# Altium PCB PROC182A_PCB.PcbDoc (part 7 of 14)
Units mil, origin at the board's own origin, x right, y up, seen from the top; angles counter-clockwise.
Board outline 3168.31 x 3700.79 mil, 8 copper layers (Top Layer, L2_GND1, L3_SIG1, L4_PWR1, L5_PWR2, L6_SIG2, L7_GND2, Bottom Layer), stack 58.1 mil thick; 580 components, 391 nets, 8314 pads, 4370 vias.
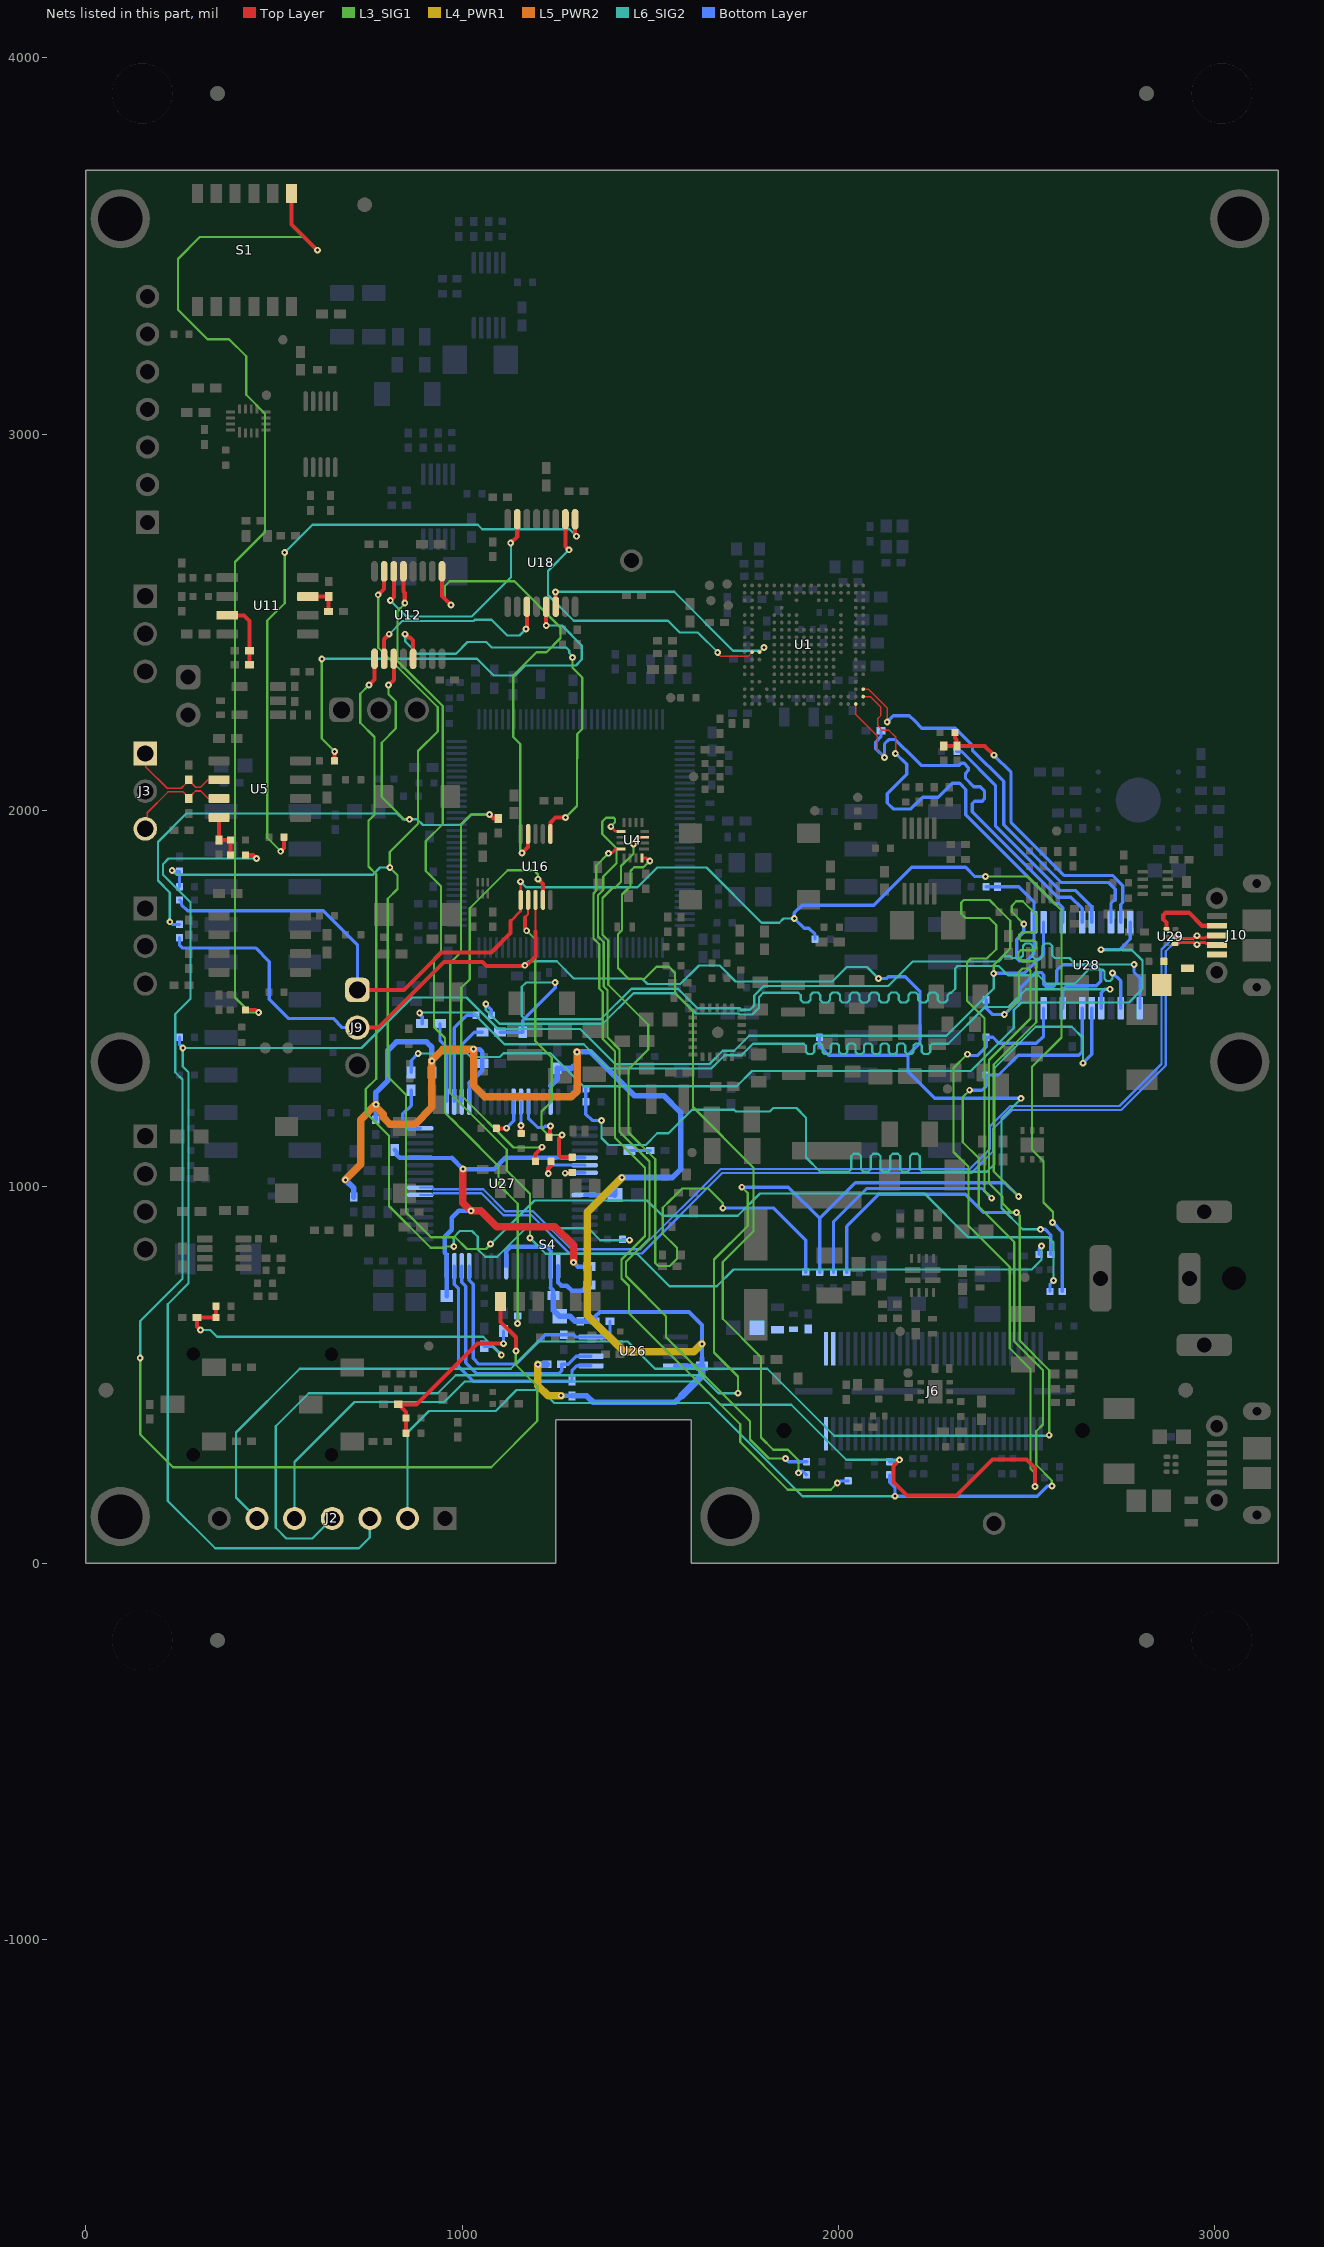
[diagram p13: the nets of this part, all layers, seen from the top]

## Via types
v1: diameter 13.77, hole 7, Top Layer to L2_GND1, tented both sides, 3444 vias
v2: diameter 18, hole 8, Top Layer to Bottom Layer, tented both sides, 911 vias
v3: diameter 13.77, hole 7, Top Layer to L2_GND1, tented top, 9 vias
v4: diameter 19.68, hole 7.87, Top Layer to Bottom Layer, 4 vias
v5: diameter 19.68, hole 7.87, Top Layer to Bottom Layer, tented both sides, 2 vias

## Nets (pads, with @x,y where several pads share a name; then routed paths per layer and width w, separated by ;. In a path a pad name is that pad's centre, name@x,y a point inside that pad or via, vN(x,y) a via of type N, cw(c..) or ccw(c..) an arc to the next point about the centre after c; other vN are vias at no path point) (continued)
CAN_FD_B_STB_CTRL: R133.1 S1.1 | length 2830.3
  Top Layer w10.8: R133.1@424.37,1470.14 450.83,1470.14 457.54,1463.43 v2(459.49,1463.43) ; S1.1@546.89,3639.18 546.89,3557.53 v2@615.88,3488.54
  L3_SIG1 w6: v2(459.49,1463.43) 436.82,1463.43 396.85,1503.4 396.85,2660.24 476.55,2739.94 476.55,3054.08 426.18,3104.45 426.18,3206.69 380.91,3251.97 323.82,3251.97 245.08,3330.71 245.08,3465.55 303.15,3523.62 581.13,3523.62 v2(616.05,3488.71)
CAN_FD_H: J3.3 R68.2 U5.7 | length 283.8
  Top Layer w4.3: J3.3@158.23,1951.41 163.25,1956.42 163.25,1994.38 218.41,2049.54 258.93,2049.54 266.49,2041.98 266.49,2041.51 273.71,2034.29 274.18,2034.29 R68.2@274.18,2031.85 ; R68.2@274.18,2034.64 275,2034.64 281.87,2041.51 281.87,2042.33 291.5,2051.95 305.38,2051.95 325.48,2031.85 U5.7@354.18,2031.85
CAN_FD_L: J3.1 R79.1 U5.6 | length 280.4
  Top Layer w4.3: J3.1@158.23,2151.41 159.7,2149.95 159.7,2115.98 216.34,2059.34 253.84,2059.34 266.49,2071.99 266.49,2072.19 R79.1@274.18,2079.88 ; R79.1@274.18,2081.85 R79.1@274.18,2079.88 ; U5.6@354.18,2081.85 324.93,2081.85 304.83,2061.75 292.32,2061.75 281.88,2072.19 R79.1@274.18,2079.88
CAN_FD_RX: R80.1 U18.5 | length 1216.1
  Top Layer w10.8: R80.1@661.32,2132.1 v2(661.32,2157.22) ; U18.5@1223.27,2541.56 1223.38,2541.44 1223.38,2491.76 v2(1223.5,2491.65)
  L3_SIG1 w6: v2(627.14,2402.65) 627.14,2191.4 v2(661.32,2157.22)
  L6_SIG2 w6: v2(627.14,2402.65) 628.06,2403.58 1039.61,2403.58 1084.25,2358.93 1141.19,2358.93 1167.77,2385.51 1302.58,2385.51 1318.08,2401.02 1318.08,2438.63 1265.06,2491.65 v2(1223.5,2491.65)
CAN_FD_TX: R78.1 U18.9 | length 1734.2
  Top Layer w10.8: v2(518.09,1891.85) 527.16,1900.92 R78.1@527.16,1929.49 ; U18.9@1300.04,2773.84 1300.04,2734.71 1304.03,2730.71 v2(1304.03,2728.77)
  L3_SIG1 w6: v2(518.09,1891.85) 482.32,1927.61 482.32,2504.74 528.65,2551.07 v2(528.65,2685.28)
  L6_SIG2 w6: v2(528.65,2685.28) 602.53,2759.16 1041.56,2759.16 1053.23,2747.48 1285.47,2747.48 1304.03,2728.92 v2(1304.03,2728.77)
CAN_FD_UARTA_RX: U1.R10 U18.6 | length 679
  Top Layer w4: U1.R10@1789.96,2420.95 v2(1801.98,2432.97)
  Top Layer w10.8: v2(1248.01,2581) 1248.43,2580.57 1248.43,2541.98 U18.6@1248.86,2541.56
  L6_SIG2 w6: v2(1248.01,2581) 1563.38,2581 1719.74,2424.64 1725.16,2424.64 1793.65,2424.64 v2(1801.98,2432.97)
CAN_FD_UARTA_TX: U1.T10 U18.10 | length 844.5
  Top Layer w4: v2(1678.86,2420.27) 1678.86,2417.38 1681.99,2414.25 1681.99,2414.01 1686.24,2409.75 1759.34,2409.75 1759.41,2409.69 U1.T10@1769.84,2420.95
  Top Layer w10.8: U18.10@1274.45,2773.84 1274.45,2701.85 v2@1283.85,2692.44
  L6_SIG2 w6: v2(1284.02,2692.61) 1228.01,2636.6 1228.01,2572.71 1296.4,2504.32 1528.36,2504.32 1546.86,2504.32 1578.1,2473.08 1626.05,2473.08 v2(1678.86,2420.27)
CAN_STB: R3.2 R71.2 R273.2 U5.8 | length 130
  Top Layer w10.8: U5.8@354.18,1981.85 R71.2@354.18,1921.85 R273.2@384.18,1921.85 R3.2@384.18,1881.85
CAN_STB_CTRL: R3.1 S4.1 | length 3404.8
  Top Layer w10.8: R3.1@424.54,1881.85 443.94,1881.85 v2(453.42,1872.37) ; S4.1@1102.05,696.11 1102.05,641.32 1142.63,600.73 v2@1142.63,564.15
  L3_SIG1 w6: v2(144.58,545.5) 144.58,342.66 231.61,255.63 1077.48,255.63 1199.92,378.07 1199.92,470.39 1142.8,527.5 v2(1142.8,564.32)
  L6_SIG2 w6: v2(144.58,545.5) 144.58,644.09 256.92,756.42 256.92,1285.62 237.87,1304.66 237.87,1459.33 278.65,1500.11 278.65,1756.12 205.04,1829.73 205.04,1857.47 219.94,1872.37 v2(453.42,1872.37)
CONN_5V: C92.1 C93.1 C96.2 J6.1 J6.2 J6.3 R30.2
DCA_LP_FTDI_HOST_INTR_1: R81.2 R261.2 R276.1 U28.10 | length 844.1
  Top Layer w10.8: R261.2@2279.02,2171.26 R276.1@2314.66,2171.26 2388.4,2171.26 v2(2412.68,2146.98) ; R81.2@2309.66,2207.46 2309.66,2192.43 2313.92,2188.16 R276.1@2313.92,2171.99
  Bottom Layer w8.7: v2(2412.68,2146.98) 2458.34,2101.33 2458.34,1968.09 2598.73,1827.7 2727.89,1827.7 2754.82,1800.77 2754.82,1755.73 2749.5,1750.41 U28.10@2749.5,1703.39
DCA_LP_FTDI_SPIA_CLK: U1.A16 U28.4 | length 1098.2
  Top Layer w4: U1.A16@2065.55,2302.84 2084.3,2302.84 2106.07,2281.07 ; 2106.07,2281.02 2112.52,2274.57 2112.52,2252.89 2103.92,2244.29 2103.92,2225.77 2116.6,2213.08 2134.36,2213.08 2151.5,2195.94 2151.5,2152.18 v2(2150.88,2151.56)
  Bottom Layer w8.7: v2(2150.88,2151.56) 2152.36,2151.56 2180.91,2123.02 2180.91,2096.81 2129.09,2044.99 2129.09,2020.1 2130.39,2018.79 2144.82,2004.36 2191.85,2004.36 2223.21,2035.72 2265.05,2035.72 2301.69,2072.36 2321.66,2072.36 2338.05,2055.98 2338.05,1989.12 2574.58,1752.59 2585.73,1752.59 2595.96,1742.37 U28.4@2595.96,1703.39
DCA_LP_FTDI_SPIA_CS: R246.1 U1.B17 U28.6 | length 1169.8
  Top Layer w4: U1.B17@2045.87,2283.16 2045.87,2254.99 2102.23,2198.63 2102.23,2161.2 v2(2122.12,2141.31)
  Bottom Layer w8.7: R246.1@2112.64,2211.9 2112.64,2195.7 2098.99,2182.05 2098.99,2164.44 v2(2122.12,2141.31) 2122.12,2177.1 2133.61,2188.58 2151.28,2188.58 2202.13,2137.73 2219.93,2119.93 2320.64,2119.93 2326.27,2125.56 2333.48,2125.56 2345.24,2113.8 2345.24,2106.59 2337.49,2098.85 2337.49,2085.16 2359.34,2063.31 2376.51,2063.31 2387.73,2052.09 2387.73,2030.96 2381.86,2025.09 2361.74,2025.09 2355.45,2018.8 2355.45,1996.33 2581.79,1769.99 2617.16,1769.99 2647.14,1740.01 U28.6@2647.14,1703.39
DCA_LP_FTDI_SPIA_MISO: R284.1 U28.7 | length 633.5
  Bottom Layer w8.7: R284.1@2314.15,2157 2326.64,2157 2416.96,2066.69 2416.96,1959.43 2588.99,1787.39 2630.12,1787.39 2672.73,1744.79 U28.7@2672.73,1703.39
DCA_LP_FTDI_SPIA_MOSI: U1.A15 U28.9 | length 1092.7
  Top Layer w4: U1.A15@2065.55,2322.53 2079.43,2322.53 2129.61,2272.35 2129.61,2235.61 v2(2129.35,2235.35)
  Bottom Layer w8.7: v2(2129.35,2235.35) 2145.82,2251.82 2188.38,2251.82 2202.13,2238.07 2221.17,2219.04 2309.95,2219.04 2355.85,2173.13 2355.85,2160.11 2438.63,2077.33 2438.63,1962.36 2592.4,1808.59 2717.78,1808.59 2734.98,1791.4 2734.98,1764.7 2723.91,1753.63 U28.9@2723.91,1703.39
DCA_LP_FTDI_UARTA_RX: U12.5 U16.6 | length 1119.4
  Top Layer w10.8: v2(848.58,2468.46) 857.66,2459.37 862.05,2459.37 869.69,2451.74 U12.5@869.69,2403.24 ; U16.6@1234.33,1937.85 1234.33,1967.62 1248.53,1981.82 v2(1274.86,1981.82)
  L3_SIG1 w6: v2(1274.86,1981.82) 1305.42,2012.38 1305.42,2137.94 1305.89,2138.42 1305.89,2203.53 1319.37,2217 1319.37,2353.41 1293.22,2379.55 v2(1293.22,2406.58)
  L6_SIG2 w6: v2(848.58,2468.46) 848.58,2449.12 880.82,2416.87 983.69,2416.87 1014.33,2447.51 1063.91,2447.51 1078.44,2432.99 1276.49,2432.99 1284.28,2425.2 1284.28,2418.77 1293.22,2409.83 v2(1293.22,2406.58)
DCA_LP_FTDI_UARTA_TX: U12.9 U16.9 | length 1253.4
  Top Layer w10.8: U12.9@946.46,2635.52 946.46,2569.55 v2@970.08,2545.93 ; v2(1159.01,1887.21) 1175.28,1903.47 U16.9@1175.28,1937.85
  L3_SIG1 w6: v2(970.25,2546.1) 954.15,2562.2 954.15,2595.9 967.26,2609 1138.91,2609 1261.53,2486.38 1261.53,2458.4 1224.04,2420.91 1197.38,2420.91 1135.65,2359.19 1135.65,2195.25 1154.18,2176.73 1154.18,1895.29 1159.01,1890.46 v2(1159.01,1887.21)
DCA_LP_HOST_INTR_1: J2.2 R42.2 R223.2 U28.19 | length 3822.9
  L3_SIG1 w6: v2(2348.55,1257.21) 2330.31,1238.98 2330.31,1118.66 2372.28,1076.69 2372.28,948.38 2466.83,853.83 2466.83,589.3 2543.31,512.82 2543.31,369.1 2525.29,351.08 2525.29,261.72 2566.78,220.24 v2(2566.78,205.6)
  L6_SIG2 w6: J2.2@854.92,119.45 854.92,347.72 911.95,404.75 1089.08,404.75 1144.75,460.42 1210.38,460.42 1244.66,426.14 1656.69,426.14 1904.34,178.48 v2(2150.09,178.48)
  Bottom Layer w8.7: R42.2@2136.06,235.06 2136.06,215.15 2150.09,201.11 v2(2150.09,178.48) ; v2@2150.48,178.48 2527.71,178.48 2554.52,205.29 2566.46,205.29 v2(2566.78,205.6) ; v2(2348.55,1257.21) 2381.42,1257.21 2392.35,1268.15 R223.2@2392.35,1297.45 2425.01,1297.45 2477.61,1350.04 2589.68,1350.04 2638.33,1350.04 2647.14,1358.85 U28.19@2647.14,1475.05
DCA_LP_RS232_RX: R61.1 R163.1 R178.1 U12.3 | length 4502.4
  Top Layer w10.8: v2(804.3,2333.27) 818.51,2347.48 U12.3@818.51,2403.24 ; v2(1072.67,1989.7) 1083.03,1979.33 R163.1@1096.46,1979.33
  L3_SIG1 w6: v2(804.3,2333.27) 804.3,2309.13 823.95,2289.48 823.95,2218.07 786.15,2180.26 786.15,2035.99 845.35,1976.79 v2(859.91,1976.79) ; v2(1072.67,1989.7) 1022.63,1989.7 996.71,1963.77 996.71,1623.39 968.29,1594.97 968.29,1248.86 1118.43,1098.72 1118.43,1043.93 1180.06,982.3 v2(1180.06,864.54)
  L6_SIG2 w6: v2(223.44,1704.32) 223.44,1782.56 191.86,1814.15 191.86,1916.36 267.4,1991.91 827.13,1991.91 842.25,1976.79 880.58,1976.79 895.85,1961.52 997.21,1961.52 1025.39,1989.7 v2(1072.67,1989.7) ; v2(1180.06,864.54) 1221.87,822.72 1464.89,822.72 1551.15,736.46 1676.67,736.46 1721.25,781.04 2513.32,781.04 2539.19,806.91 v2(2539.19,843.38)
  Bottom Layer w8.7: v2(223.44,1704.32) 230.32,1697.45 R178.1@249.2,1697.45 ; R61.1@2532.48,820.37 2532.48,834.15 2539.19,840.86 v2(2539.19,843.38)
DCA_LP_RS232_TX: R62.1 R156.1 R176.1 U12.15 | length 4562.3
  Top Layer w10.8: v2@776.78,2573.07 v2(776.95,2573.24) 792.92,2589.21 U12.15@792.92,2635.52
  L3_SIG1 w6: v2(776.95,2573.24) 776.95,2432.3 934.91,2274.33 934.91,2210.37 882.8,2158.25 882.8,1964.74 807.81,1889.75 v2(807.81,1848.89) 828.59,1828.12 828.59,1791.84 802.41,1765.67 802.41,1293.54 850.97,1244.98 850.97,932.91 917.39,866.48 981.8,866.48 1012.78,835.5 1063.44,835.5 1075.22,847.28 v2(1075.22,848.27)
  L6_SIG2 w6: v2(229.76,1840.97) 240.94,1829.79 762.94,1829.79 782.04,1848.89 v2(807.81,1848.89) ; v2(1075.22,848.27) 1076.21,848.27 1192.28,964.35 1491.24,964.35 1532.08,923.52 1732.28,923.52 1791.39,982.62 2228.19,982.62 2344.08,866.73 2556.77,866.73 2563.96,859.54 2571.29,852.21 v2(2571.29,751.51)
  Bottom Layer w8.7: v2(229.76,1840.97) 232.28,1840.97 235.8,1837.45 R156.1@249.2,1837.45 R176.1@249.2,1797.45 ; R62.1@2561.82,722.42 2561.82,742.04 v2(2571.29,751.51)
DCA_LP_SPIA_CLK: J2.3 R41.1 R210.1 U28.2 | length 6423
  L3_SIG1 w6: v2(2406.88,970.16) 2387.71,989.34 2387.71,1448.52 2341.55,1494.67 2341.55,1597.11 2351.32,1606.88 2393.79,1606.88 2418.68,1631.77 2418.68,1696.09 2400.39,1714.38 2337,1714.38 2325.76,1725.63 2325.76,1755.5 2332.97,1762.71 2400.89,1762.71 2428.36,1735.24 2456.34,1707.26 2456.34,1633.5 2412.22,1589.39 v2(2412.22,1566.86)
  L6_SIG2 w6: J2.3@754.92,119.45 754.92,68.9 726,39.98 343.88,39.98 217.87,165.99 217.87,688.71 273.31,744.16 273.31,1304.5 257.87,1319.94 v2(257.87,1369.43) 732.87,1369.43 866.61,1503.17 1011.62,1503.17 1095,1419.78 1313.68,1419.78 1406.82,1326.65 1657.04,1326.65 1692.46,1362.07 1723.06,1362.07 1762.71,1401.72 2286.56,1401.72 2412.22,1527.38 v2(2412.22,1566.86)
  Bottom Layer w8.7: R210.1@249.2,1397.45 249.2,1378.1 v2(257.87,1369.43) ; R41.1@1986.6,772.75 1986.6,908.09 2074.39,995.88 2381.16,995.88 v2(2406.88,970.16) ; v2(2412.22,1566.86) 2413.5,1568.14 2493.98,1568.14 2544.77,1618.93 U28.2@2544.77,1703.39
DCA_LP_SPIA_CS: J2.4 R39.1 R173.1 R177.2 U28.1 | length 4903.5
  L3_SIG1 w6: v2(1733.04,452.23) 1733.04,496.29 1669.15,560.18 1669.15,807.21 1758.51,896.57 1758.51,983.98 v2(1742.96,999.53) ; v2(2478.62,974.66) 2412.43,1040.84 2412.43,1325.2 2524.95,1437.71 2524.95,1593.63 2519.08,1599.49 2487.14,1599.49 2477.97,1608.67 2477.97,1622.65 2484.25,1628.94 2519.34,1628.94 2524.95,1634.54 2524.95,1649.87 2520.53,1654.29 2485.36,1654.29 2480.26,1659.39 2480.26,1669.84 2487.14,1676.72 2520.97,1676.72 2524.95,1680.69 2524.95,1723.66 2489.62,1758.98 2472.35,1758.98 2459.97,1746.61 2459.97,1731.09 v2(2492.18,1698.88)
  L6_SIG2 w6: J2.4@654.92,119.45 601.82,66.34 533.07,66.34 505.09,94.32 505.09,364.34 592.59,451.84 935.11,451.84 983.27,500 1633.52,500 1681.3,452.23 v2(1733.04,452.23)
  Bottom Layer w8.7: v2(1742.96,999.53) 1866.63,999.53 1949.84,916.32 ; R39.1@1949.84,772.75 1949.84,916.32 ; R177.2@2392.35,1797.45 R173.1@2422.35,1797.45 2479.19,1797.45 2519.18,1757.46 U28.1@2519.18,1703.39 2519.18,1619.83 2500.41,1601.06 2480.05,1601.06 2473.43,1607.68 2473.43,1657.69 2492.18,1676.45 v2(2492.18,1698.88) ; v2(2478.62,974.66) 2441.98,1011.3 2044.82,1011.3 1949.84,916.32
DCA_LP_SPIA_MISO: J2.5 R53.2 R221.2 U28.23 | length 4087.5
  Top Layer w10.8: v2(2161.63,275.08) 2145.67,259.12 2145.67,215.6 2181.33,179.93 2313.19,179.93 2409.29,276.04 2499.95,276.04 2522.1,253.88 v2(2522.1,204.37)
  L3_SIG1 w6: v2(2342.3,1352.6) 2305.48,1315.78 2305.48,1092.93 2345.02,1053.39 2345.02,897.09 2454.83,787.29 2454.83,571.25 2510.3,515.78 2510.3,251.68 2522.1,239.88 v2(2522.1,204.37)
  L6_SIG2 w6: J2.5@554.92,119.45 554.92,269.49 714.36,428.93 952.55,428.93 1006.89,483.27 1624.36,483.27 1686.47,421.15 1874.44,421.15 2020.51,275.08 v2(2161.63,275.08)
  Bottom Layer w8.7: R53.2@2135.45,270.03 2156.58,270.03 v2(2161.63,275.08) ; v2@2349.57,1349.16 2368.97,1349.16 2392.35,1372.55 R221.2@2392.35,1397.45 2410.37,1397.45 2426.24,1381.58 2525.77,1381.58 2544.77,1400.59 U28.23@2544.77,1475.05
DCA_LP_SPIA_MOSI: J2.6 R52.1 R201.2 U28.21 | length 5429.5
  L3_SIG1 w6: v2(2440.54,1457.95) 2479.6,1497.01 2479.6,1571.64 2488.43,1580.47 2503.15,1580.47 2509.98,1573.64 2509.98,1447.49 2399.71,1337.22 2399.71,1009.8 2434.75,974.76 2434.75,957.09 2459.48,932.37 v2(2472.96,932.37) 2481.12,924.21 2481.12,591.97 2559.75,513.35 v2(2559.75,340.51)
  L6_SIG2 w6: J2.6@454.92,119.45 399.19,175.18 399.19,347.7 568.58,517.08 1128.94,517.08 1201.42,589.57 1439.96,589.57 1512.44,517.09 1810.67,517.09 1988.8,338.96 2558.19,338.96 v2(2559.75,340.51)
  Bottom Layer w8.7: R52.1@2021.6,773.19 2021.6,895.09 2106.84,980.33 2336.41,980.33 2384.37,932.37 v2(2472.96,932.37) ; R201.2@2392.35,1497.45 2392.35,1474.71 2409.11,1457.95 v2(2440.54,1457.95) 2483.02,1500.43 2483.02,1528.44 2524.42,1569.84 2538.22,1569.84 2545.27,1562.79 2545.27,1538.06 2551.3,1532.03 2570,1532.03 2579.83,1541.86 2579.83,1575.15 2595.03,1590.35 2680.53,1590.35 2696.68,1574.2 2696.68,1546.08 2685.26,1534.66 2605.6,1534.66 2595.96,1525.01 U28.21@2595.96,1475.05
DCA_LP_UARTA_RX: J9.2 R152.2 R198.1 R212.1 U16.3 | length 3868.7
  Top Layer w6: 1194.96,1678.51 U16.3@1194.96,1762.65
  Top Layer w10.8: J9.2@721.75,1423.37 777.37,1423.37 952.04,1598.03 1054.65,1598.03 1065.2,1587.48 v2@1169.76,1587.48 ; v2(1166.6,1588.75) 1168.55,1588.75 1172.15,1592.35 1174.63,1592.35 1194.96,1612.68 1194.96,1678.51
  L6_SIG2 w6: v2(1166.6,1588.75) 1166.6,1589.85 1176.11,1599.37 1251.1,1599.37 1296.59,1553.88 1477.53,1553.88 1492.5,1538.91 1579.69,1538.91 1629.04,1588.26 1684.12,1588.26 1726.48,1545.89 1983.49,1545.89 2021.86,1584.26 2075.59,1584.26 v2(2105.96,1553.89) ; v2(2485.02,1235.48) 2485.02,1234.29 2463.11,1212.39 2433.03,1182.31 2433.03,944.02 2489.49,887.55 v2(2536.34,887.55)
  Bottom Layer w8.7: R198.1@249.2,1662.45 249.2,1641.77 255.85,1635.13 451.25,1635.13 487.46,1598.92 487.46,1498.29 538.1,1447.65 657.51,1447.65 681.79,1423.37 J9.2@721.75,1423.37 ; R212.1@1949.2,1397.45 1949.2,1374.67 1973.59,1350.28 2184.3,1350.28 ; v2(2105.96,1553.89) 2128.12,1553.89 2132.36,1558.13 2177.13,1558.13 2216.52,1518.74 2216.52,1382.5 2184.3,1350.28 ; v2(2485.02,1235.48) 2255.81,1235.48 2184.3,1306.99 2184.3,1350.28 ; v2(2536.34,887.55) 2548.78,887.55 2563.98,872.35 R152.2@2563.98,820.87
DCA_LP_UARTA_TX: J9.1 R153.2 R180.1 R182.1 U16.1 | length 4070.8
  Top Layer w7: 1128.83,1705.92 1155.59,1732.68 U16.1@1155.59,1762.65 1155.59,1810.19 v2(1154.8,1810.99)
  Top Layer w10.8: J9.1@721.75,1523.37 845.57,1523.37 945.07,1622.86 1077.37,1622.86 1128.83,1674.32 1128.83,1705.92
  L3_SIG1 w6: v2(2390.55,1824.57) 2502.69,1824.57 2592.05,1735.22 2592.05,1397.34 2514.05,1319.34 2514.05,1098.63 2544.67,1068.01 2544.67,958.6 2569.6,933.67 2569.6,906.58 v2(2568.81,905.78)
  L6_SIG2 w6: v2(1154.8,1810.99) 1169.54,1796.25 1466.17,1796.25 1518.34,1848.42 1649.1,1848.42 1795.65,1701.87 1842.59,1701.87 1853.97,1713.25 v2(1882.65,1713.25)
  Bottom Layer w8.7: R180.1@249.2,1762.45 254.2,1757.45 254.2,1750.32 270.49,1734.03 631.49,1734.03 721.75,1643.77 J9.1@721.75,1523.37 ; R182.1@1937.71,1658.52 1937.71,1670.86 1920.99,1687.58 1908.32,1687.58 v2(1882.65,1713.25) 1882.65,1728.04 1903.01,1748.41 2093.6,1748.41 2194.62,1849.43 2337.7,1849.43 2362.56,1824.57 v2(2390.55,1824.57) ; v2(2568.81,905.78) 2594.47,880.12 R153.2@2594.47,722.42
DCA_TCK: R38.2 U4.16 | length 2124
  Top Layer w7: U4.16@1477.36,1874.02 1488.92,1874.02 1496.73,1866.21 v2(1498.62,1866.21)
  L3_SIG1 w6: v2(1498.62,1866.21) 1482.1,1849.69 1457.27,1849.69 1447.22,1839.64 1447.22,1799.4 1424.53,1776.71 1424.53,1682.25 1413.95,1671.68 1413.95,1581.44 1442.62,1552.77 1484.18,1552.77 1516.22,1584.82 1549.44,1584.82 1565.83,1568.44 1565.83,1514.33 1613.19,1466.96 1613.19,1340.77 1613.18,1212.5 1774.29,1051.39 1774.29,882.19 1692.5,800.4 1692.5,649.64 1794.29,547.85 1794.29,334.65 1826.77,302.17 1865.88,302.17 1893.95,274.09 v2(1893.95,240.69)
  Bottom Layer w8.7: v2(1893.95,240.69) 1896.01,240.69 1900.2,244.87 1905.51,244.87 1914.83,235.55 R38.2@1914.83,235.06
DCA_TDI: R37.1 U4.3 | length 2062.5
  Top Layer w7: v2(1454.98,1910.64) 1454.98,1913.18 1470.93,1929.13 U4.3@1485.24,1929.13
  L3_SIG1 w6: v2(1454.98,1910.64) 1454.98,1885.58 1421.98,1852.58 1421.98,1810.9 1406.81,1795.73 1401.11,1795.73 1372.85,1767.47 1372.85,1670.31 1388.11,1655.05 1388.11,1537.4 1494.38,1431.13 1494.38,1365.44 1441.86,1312.92 1441.86,1144.66 1512.82,1073.69 1512.82,798.15 1520.87,790.1 1551.61,790.1 1570.63,809.12 1570.63,838.52 1533.18,875.96 1533.18,944.82 1553.45,965.09 1553.74,965.09 1565.45,976.8 1565.45,977.09 1584.49,996.13 1653.92,996.13 1692.67,957.37 v2(1692.67,943.52)
  Bottom Layer w8.7: v2(1692.67,943.52) 1693.09,943.93 1827.76,943.93 1912.63,859.06 R37.1@1912.63,773.64
DCA_TDO: R34.2 U4.9 | length 2170
  Top Layer w7: v2(1394.94,1957.23) 1407.29,1944.88 U4.9@1422.24,1944.88
  L3_SIG1 w6: v2(1394.94,1957.23) 1406.35,1968.65 1406.35,1977.7 1402.83,1981.21 1382.2,1981.21 1372.21,1971.22 1372.21,1937.53 1410.03,1899.71 1410.03,1860.34 1374.73,1825.03 1374.73,1788.86 1360.85,1774.98 1360.85,1665.34 1376.11,1650.08 1376.11,1532.43 1385.91,1522.63 1385.91,1397.93 1418.38,1365.46 1418.38,1146.91 1497.58,1067.71 1497.58,863.59 1435.23,801.24 1435.23,763.17 1541.81,656.59 1541.81,600.65 1764.8,377.66 1764.8,328.89 1815.28,278.41 v2(1859.04,278.41)
  Bottom Layer w8.7: v2(1859.04,278.41) 1859.04,277.92 1866.93,270.03 R34.2@1915.43,270.03
DCA_TMS: R40.2 U4.12 | length 2180.8
  Top Layer w7: v2(1389.15,1886.55) 1391.25,1888.65 1398.95,1888.65 1407.93,1897.64 U4.12@1422.24,1897.64
  L3_SIG1 w6: v2(1389.15,1886.55) 1356.28,1853.68 1356.28,1787.38 1348.85,1779.95 1348.85,1660.37 1364.11,1645.11 1364.11,1527.46 1373.91,1517.66 1373.91,1392.96 1406.38,1360.49 1406.38,1130.43 1485.58,1051.22 1485.58,869.56 1423.23,807.21 1423.23,757.09 1443.62,736.7 1443.62,664.67 1738.59,369.71 1738.59,322.38 1865.27,195.7 1979.06,195.7 v2(1996.62,213.26)
  Bottom Layer w8.7: v2(1996.62,213.26) 1999.14,213.26 2004.44,218.56 2024.51,218.56 R40.2@2025.44,219.5
EECLK: R167.1 U26.2 U27.62 | length 634.8
  Bottom Layer w8.7: U27.62@999.11,789.79 999.11,746.27 1009.67,735.71 1009.67,533.43 1039.17,503.94 1256.12,503.94 1264.36,512.18 R167.1@1264.36,528.88 ; R167.1@1264.39,528.85 1281.86,528.85 1303.33,550.33 U26.2@1342.51,550.33
EECS: R168.1 U26.1 U27.63 | length 672.8
  Bottom Layer w8.7: U27.63@979.43,789.79 979.43,741.05 990.47,730.01 990.47,522.59 1029.46,483.6 1290.93,483.6 R168.1@1291.83,484.49 1291.83,511.46 1305.11,524.74 U26.1@1342.51,524.74
EEDATA: R184.1 R185.1 U26.4 U27.61 | length 690.9
  Bottom Layer w8.7: U27.61@1018.8,789.79 1018.8,752.35 1029.4,741.76 1029.4,544.54 1044.52,529.42 1142.91,529.42 1220.8,607.31 R185.1@1270.18,607.31 1296.26,607.31 1302.07,601.51 U26.4@1342.51,601.51 1384.36,601.51 1392.88,610.03 R184.1@1392.88,643.29
EEPROM_A2: R161.1 R162.2 U11.3 | length 95
  Top Layer w10.8: U11.3@590.19,2568.79 R162.2@645.19,2568.79 R161.1@645.19,2528.79
EEPROM_WPn: R157.1 R158.2 U11.7 | length 181.4
  Top Layer w10.8: U11.7@376.18,2518.23 420.37,2518.23 435.36,2503.23 R157.1@435.36,2424.24 R158.2@435.36,2387.24
FTDI_3V3: C138.1 C149.2 C150.1 C151.2 C152.1 C153.1 L2.1 L3.1 L7.2 R167.2 R168.2 R184.2 R237.1 U26.8 U27.20 U27.31 U27.42 U27.50 U27.56 | length 5061.4
  L5_PWR2 w20: v2(689.55,1019.13) 730.24,1059.82 730.24,1178.9 v2(770.93,1219.59) ; v2@771.65,1211.62 790.03,1193.24 790.03,1185.49 808.41,1167.11 875.07,1167.11 919.56,1211.6 v2(919.56,1334.86) ; v2@919.43,1336.22 919.75,1336.54 949.22,1366.01 v2(1030.44,1366.01) 1030.44,1269.36 1060.68,1239.13 1290.21,1239.13 1305.57,1254.48 1305.57,1358.13 v2(1304.88,1358.82)
  L4_PWR1 w20: v2(1201.29,528.54) 1201.29,472.57 1228.49,445.37 v2(1263.15,445.37) ; v2(1424.21,1024.61) 1332.51,932.9 1332.51,659.35 1430.18,561.67 1615.44,561.67 v2(1637.22,583.46)
  Bottom Layer w10: U27.20@1018.8,1226.8 1018.8,1275.29 ; 1235.32,731.78 1235.32,754.55 1235.34,831.23 ; U27.31@1235.34,1226.8 1235.34,1269.13 ; U27.42@1325.89,978.77 C151.2@1405.89,978.77
  Bottom Layer w11: U27.56@1117.32,789.79 1117.32,831.23 ; R184.2@1353.51,643.29 1353.51,655.64 1366.14,668.26 1602.56,668.26 1637.22,633.6 v2(1637.22,583.46) 1636.84,583.08 1636.84,546.39
  Bottom Layer w12: 770.93,1204.59 770.93,1199.41 770.93,1178.66 L3.1@770.99,1178.6 ; 1018.8,1275.29 1053.81,1310.3 1053.81,1358.98 1046.78,1366.01 v2(1030.44,1366.01) ; 1117.32,831.23 1118.68,831.23 1128.38,840.92 1225.61,840.92 1235.31,831.23 ; v2(1201.29,528.54) v2@1201.46,528.71 ; R167.2@1224.82,528.71 R167.2@1224.99,528.88 ; 1235.34,731.76 1242.32,724.78 C150.1@1242.32,711.79 ; v2(1263.15,445.37) 1263.27,445.25 1291.7,445.25 R168.2@1291.83,445.12
  Bottom Layer w13: U26.8@1566.92,524.74 C138.1@1636.84,524.74 ; 1636.84,546.39 1636.84,524.81 C138.1@1636.92,524.74
  Bottom Layer w15: v2(689.55,1019.13) 712.28,996.41 L2.1@712.28,973.04 ; 770.93,1204.59 770.93,1250.86 802.08,1282.01 802.08,1361.87 825.8,1385.59 905.26,1385.59 919.43,1371.42 919.43,1334.99 v2(919.56,1334.86) ; R237.1@919.5,1304.08 v2@919.5,1336.15 ; 1235.34,1269.13 1252.76,1286.55 C152.1@1252.76,1315.55 1290.86,1315.55 1304.88,1329.58 v2(1304.88,1358.82) 1341.8,1358.82 1458.2,1242.41 1536.35,1242.41 1580.52,1198.24 1580.52,1046.87 1558.61,1024.97 1423.74,1024.97 1405.89,1007.11 C151.2@1405.89,978.77 ; C150.1@1242.32,711.79 1242.32,672.57 1258.43,656.45 C149.2@1259.42,656.45 1286.61,656.45 1299.77,643.29 L7.2@1313.51,643.29 R184.2@1353.51,643.29 ; R168.2@1291.83,445.12 1331.17,445.12 1348.22,428.07 1566.03,428.07 1583.08,445.12
  Bottom Layer w18: v2@1201.46,528.71 R167.2@1224.82,528.71
  Bottom Layer w20: 1583.08,445.12 1636.84,498.89 1636.84,524.74 C138.1@1636.84,524.81
FTDI_12C_SDA_IN: R100.1 U27.27 | length 84.5
  Top Layer w10.8: v2(1156.57,1162.98) 1156.66,1162.89 1156.66,1142.48 R100.1@1156.74,1142.4
  Bottom Layer w8.7: v2(1156.57,1162.98) U27.27@1156.59,1226.8
FTDI_12C_SDA_OUT: R102.1 U27.28 | length 145.8
  Top Layer w10.8: R102.1@1231.31,1131.76 1233.59,1134.04 1233.59,1160.29 v2(1234.97,1161.67)
  Bottom Layer w8.7: U27.28@1176.28,1226.8 1176.28,1182.9 1201.18,1158 1217.27,1158 1220.94,1161.67 v2(1234.97,1161.67)
FTDI_DCA_LP_RS232_RX: U12.2 U18.3 | length 534.6
  Top Layer w10.8: U12.2@792.92,2403.24 792.92,2455.11 v2(806.27,2468.46) ; v2@1169.26,2482.04 v2(1169.43,2482.21) 1172.09,2484.87 U18.3@1172.09,2541.56
  L6_SIG2 w6: v2(806.27,2468.46) 841.23,2503.41 1030.35,2503.41 1033.61,2506.68 1078.29,2506.68 1119.67,2465.3 1152.52,2465.3 v2(1169.43,2482.21)
FTDI_DCA_LP_RS232_TX: U12.14 U18.15 | length 624.6
  Top Layer w10.8: v2@809.06,2558.07 v2(809.22,2558.24) 818.51,2567.53 U12.14@818.51,2635.52 ; v2(1128.94,2710.63) 1146.5,2728.19 U18.15@1146.5,2773.84
  L6_SIG2 w6: v2(809.22,2558.24) 852.05,2515.41 1025.38,2515.41 1129.88,2619.92 1129.88,2709.69 v2(1128.94,2710.63)
FTDI_HOST_INTR_1: R216.2 R217.2 U28.18 | length 2494.4
  L6_SIG2 w6: v2(1370.15,1176.78) 1370.15,1129.99 1388.68,1111.46 1487.7,1111.46 1518.7,1142.46 1548.1,1142.46 1610.68,1205.05 1723.22,1205.05 1727.92,1200.35 1817.48,1200.35 1826.72,1209.58 1888.01,1209.58 1913.49,1184.11 1913.49,1078.57 1951.7,1040.36 1997.36,1040.36 2027.15,1040.36 2033.65,1046.86 2033.65,1081.89 2040.15,1088.39 2053.15,1088.39 2059.65,1081.89 2059.65,1046.81 2066.15,1040.31 2079.15,1040.31 2085.65,1046.81 2085.65,1081.89 2092.15,1088.39 2105.15,1088.39 2111.65,1081.89 2111.65,1046.81 2118.15,1040.31 2131.15,1040.31 2137.65,1046.81 2137.65,1081.89 2144.15,1088.39 2157.15,1088.39 2163.65,1081.89 2163.65,1046.81 2170.15,1040.31 2183.15,1040.31 2189.65,1046.81 2189.65,1081.89 2196.15,1088.39 2209.15,1088.39 2215.65,1081.89 2215.65,1046.86 2222.15,1040.36 2251.15,1040.36 2393.94,1040.36 2413.39,1059.8 2413.39,1315.12 2523.93,1425.67 2619.44,1425.67 2649.26,1395.84 v2(2649.26,1328.81)
  Bottom Layer w8.7: R216.2@1328.65,1261.32 R217.2@1328.65,1226.32 1328.65,1193.46 1345.33,1176.78 v2(1370.15,1176.78) ; v2(2649.26,1328.81) 2672.73,1352.28 U28.18@2672.73,1475.05
FTDI_I2C_SCL: R96.1 U27.26 | length 105.5
  Top Layer w10.8: R96.1@1090.96,1155.7 1091.12,1155.87 1117.41,1155.87 v2(1117.57,1156.03)
  Bottom Layer w8.7: v2(1117.57,1156.03) 1136.91,1175.37 U27.26@1136.91,1226.8
FTDI_MISO: R189.1 U27.18 | length 267.3
  Bottom Layer w8.7: U27.18@979.43,1226.8 979.41,1422.58 1012.74,1455.91 R189.1@1037.18,1455.91
FTDI_MOSI: R187.1 U27.17 | length 214.8
  Bottom Layer w8.7: R187.1@941.09,1433.88 941.09,1389.97 959.74,1371.31 U27.17@959.74,1226.8
FTDI_RS232_RX: R120.2 U12.1 | length 2366.5
  Top Layer w10.8: v2(752.42,2333.27) 767.33,2348.18 U12.1@767.33,2403.24
  L3_SIG1 w6: v2(752.42,2333.27) 729.63,2310.48 729.63,2233.12 767.51,2195.24 767.51,1989.11 751.02,1972.62 751.02,1851.64 771.68,1830.98 771.68,1287.62 744.09,1260.04 744.09,1197.75 805.55,1136.29 805.55,949.59 916.6,838.54 954.91,838.54 958.33,841.95 977.61,841.95 v2(977.83,842.17)
  L6_SIG2 w6: v2(977.83,842.17) 977.83,866.69 993.96,882.82 1025.96,882.82 1041.22,867.56 1041.22,834.19 1061.14,814.27 1093.36,814.27 1169.09,890 1335.46,890 1366.84,858.62 v2(1444.59,858.62)
  Bottom Layer w8.7: R120.2@1426.24,860.66 1427.26,859.64 1443.57,859.64 v2(1444.59,858.62)
FTDI_RS232_TX: R121.2 U12.13 | length 2213.5
  Top Layer w10.8: U12.13@844.1,2635.52 844.1,2582.03 847.61,2578.52 v2(847.61,2551.43)
  L3_SIG1 w6: v2(847.61,2551.43) 847.61,2549.33 828.58,2530.29 828.58,2397.64 948.48,2277.74 948.48,1963.86 903.55,1918.93 903.55,1839.27 944.07,1798.74 944.07,1626.43 925.03,1607.38 925.03,1425.27 954.7,1395.59 954.7,1197.13 984.83,1167.01 984.83,1166.81 996.54,1155.09 996.75,1155.09 1096.46,1055.38 1096.46,1006.25 1147.53,955.18 1147.53,637.83 v2(1147.12,637.41)
  Bottom Layer w8.7: v2(1147.12,637.41) 1147.43,637.72 1147.43,657.46 R121.2@1147.74,657.77
FTDI_SOP0: R13.1 R43.2 R235.1 R249.2 | length 998.3
  Top Layer w10.8: v2(305.12,620.08) 295.94,629.26 R13.1@295.94,653.31 R43.2@345.94,653.31 R235.1@345.94,683.31
  L6_SIG2 w6: v2(305.12,620.08) 330.82,620.08 349.02,601.88 1056.08,601.88 v2(1104.16,553.8)
  Bottom Layer w8.7: R249.2@1058.84,576.72 1081.24,576.72 v2(1104.16,553.8)
FTDI_SOP1: R16.1 R67.2 R244.1 R248.2 | length 464.6
  Top Layer w10.8: R244.1@850.79,346.19 R67.2@850.79,386.19 850.79,401.94 R16.1@830.34,422.39 878.92,422.39 1040.29,583.76 v2(1109.73,583.76)
  Bottom Layer w8.7: v2(1109.73,583.76) R248.2@1109.7,617.41
FTDI_SPI_CLK: R186.2 U28.11 | length 2494.5
  L6_SIG2 w6: v2(883.4,1354.86) 955.53,1354.86 955.82,1355.15 1013.02,1355.15 1022.89,1345.28 1099.82,1345.28 1109.69,1355.15 1234.53,1355.15 1322.17,1267.51 1729.51,1267.51 1770.14,1308.14 2351.44,1308.14 2465.55,1422.25 2465.55,1470.04 2485.9,1490.39 2771.44,1490.39 2807.51,1526.47 2807.51,1601.37 2778.47,1630.42 v2(2697.03,1630.42)
  Bottom Layer w8.7: R186.2@864.5,1304.02 864.5,1335.95 v2(883.4,1354.86) ; v2(2697.03,1630.42) 2746.78,1630.42 2775.09,1658.73 U28.11@2775.09,1703.39
FTDI_SPI_CS: R99.1 R209.2 U28.13 | length 2420.8
  L6_SIG2 w6: v2(1247.27,1543.1) 1170.17,1543.1 1158.74,1531.68 1158.74,1454.37 1167.61,1445.5 1368.61,1445.5 1450.02,1526.91 1573.22,1526.91 1625.26,1474.87 1737.56,1474.87 1741.47,1470.96 1765.08,1470.96 1776.43,1482.32 1776.43,1508.93 1801.4,1533.89 2132.31,1533.89 2197.27,1598.86 2424.81,1598.86 2438.93,1612.97 2456.23,1612.97 2460.84,1608.36 2462.59,1608.36 2483.38,1608.36 2489.88,1614.86 2489.88,1640.3 2496.38,1646.8 2509.38,1646.8 2515.88,1640.3 2515.88,1611.74 2522.38,1605.24 2535.38,1605.24 2541.88,1611.74 2541.88,1640.3 2548.38,1646.8 2561.38,1646.8 2567.88,1640.3 2567.88,1614.86 2574.38,1608.36 2603.38,1608.36 2613.83,1608.36 2631.1,1591.08 v2(2785.36,1591.08)
  Bottom Layer w8.7: R209.2@1101.06,1411.22 R99.1@1161.06,1411.22 1161.06,1442.44 1247.27,1528.66 v2(1247.27,1543.1) ; v2@2784.98,1591.01 2784.98,1570.97 2800.68,1555.27 U28.13@2800.68,1475.05
FTDI_SPI_MISO: R189.2 U28.15 | length 2369.7
  L6_SIG2 w6: v2(1062.97,1485.76) 1062.97,1469.93 1099.4,1433.5 1373.58,1433.5 1454.99,1514.91 1567.36,1514.91 1621.19,1461.09 1734.37,1461.09 1736.99,1458.47 1770.88,1458.47 1788.43,1476.02 1788.43,1503.96 1800.16,1515.69 1846.44,1515.69 1893.15,1515.69 1899.65,1509.19 1899.65,1496.45 1906.15,1489.95 1919.15,1489.95 1925.65,1496.45 1925.65,1509.99 1932.15,1516.49 1945.15,1516.49 1951.65,1509.99 1951.65,1496.45 1958.15,1489.95 1971.15,1489.95 1977.65,1496.45 1977.65,1509.99 1984.15,1516.49 1997.15,1516.49 2003.65,1509.99 2003.65,1496.45 2010.15,1489.95 2023.15,1489.95 2029.65,1496.45 2029.65,1509.99 2036.15,1516.49 2049.15,1516.49 2055.65,1509.99 2055.65,1496.45 2062.15,1489.95 2075.15,1489.95 2081.65,1496.45 2081.65,1509.99 2088.15,1516.49 2101.15,1516.49 2107.65,1509.99 2107.65,1496.45 2114.15,1489.95 2127.15,1489.95 2133.65,1496.45 2133.65,1509.99 2140.15,1516.49 2153.15,1516.49 2159.65,1509.99 2159.65,1496.45 2166.15,1489.95 2179.15,1489.95 2185.65,1496.45 2185.65,1509.99 2192.15,1516.49 2205.15,1516.49 2211.65,1509.99 2211.65,1496.45 2218.15,1489.95 2231.15,1489.95 2237.65,1496.45 2237.65,1509.99 2244.15,1516.49 2257.15,1516.49 2263.65,1509.99 2263.65,1496.45 2270.15,1489.95 2283.15,1489.95 2289.65,1496.45 2289.65,1509.19 2296.15,1515.69 2299.15,1515.69 2309.78,1526.32 2309.78,1580.34 2316.3,1586.86 2425.78,1586.86 2450.22,1562.41 2530.44,1562.41 2552.95,1539.9 2627.26,1539.9 2665.09,1577.73 2701.41,1577.73 2706.62,1572.52 2706.62,1553.09 2712.2,1547.51 2721.63,1547.51 2727.95,1553.84 v2(2727.95,1568.11)
  Bottom Layer w8.7: v2(1062.97,1485.76) 1077.53,1471.2 R189.2@1077.53,1455.91 ; v2(2727.95,1568.11) 2728.81,1568.11 2749.5,1547.42 U28.15@2749.5,1475.05
FTDI_SPI_MOSI: R187.2 U28.17 | length 2427.6
  L6_SIG2 w6: v2(887.32,1462.01) 889.05,1463.74 1028.15,1463.74 1112.67,1379.22 1322.9,1379.22 1387.47,1314.65 1662.01,1314.65 1697.43,1350.07 1742.22,1350.07 1772.57,1380.42 1882.89,1380.42 1907.89,1380.42 1913.39,1374.92 1913.39,1358.64 1918.89,1353.14 1929.89,1353.14 1935.39,1358.64 1935.39,1375.79 1940.89,1381.29 1951.89,1381.29 1957.39,1375.79 1957.39,1358.64 1962.89,1353.14 1973.89,1353.14 1979.39,1358.64 1979.39,1375.79 1984.89,1381.29 1995.89,1381.29 2001.39,1375.79 2001.39,1358.64 2006.89,1353.14 2017.89,1353.14 2023.39,1358.64 2023.39,1375.79 2028.89,1381.29 2039.89,1381.29 2045.39,1375.79 2045.39,1358.64 2050.89,1353.14 2061.89,1353.14 2067.39,1358.64 2067.39,1375.79 2072.89,1381.29 2083.89,1381.29 2089.39,1375.79 2089.39,1358.64 2094.89,1353.14 2105.89,1353.14 2111.39,1358.64 2111.39,1375.79 2116.89,1381.29 2127.89,1381.29 2133.39,1375.79 2133.39,1358.64 2138.89,1353.14 2149.89,1353.14 2155.39,1358.64 2155.39,1375.79 2160.89,1381.29 2171.89,1381.29 2177.39,1375.79 2177.39,1358.64 2182.89,1353.14 2193.89,1353.14 2199.39,1358.64 2199.39,1375.79 2204.89,1381.29 2215.89,1381.29 2221.39,1375.79 2221.39,1358.64 2226.89,1353.14 2237.89,1353.14 2243.39,1358.64 2243.39,1374.92 2248.89,1380.42 2280.64,1380.42 2291.6,1380.42 2389.37,1478.19 2451.78,1478.19 2498.88,1525.29 v2(2721.23,1525.29)
  Bottom Layer w8.7: v2(887.32,1462.01) 887.32,1459.5 893.85,1452.97 R187.2@893.85,1433.88 ; U28.17@2698.32,1475.05 2698.32,1515.85 2707.76,1525.29 v2(2721.23,1525.29)
FTDI_SPICLK: R186.1 U27.16 | length 149.6
  Bottom Layer w8.7: R186.1@864.5,1256.78 864.5,1216.33 842.38,1194.22 842.38,1169.34 845.25,1166.47 845.25,1164.85 854.16,1155.93 U27.16@888.88,1155.93
FTDI_SPICS: R209.1 U27.19 | length 219.5
  Bottom Layer w8.7: U27.19@999.11,1226.8 999.11,1377.67 1032.67,1411.22 R209.1@1053.81,1411.22
FTDI_SUSPEND_N: R251.2 R252.1 | length 55
  Bottom Layer w8.7: R251.2@1444.94,1096.88 R252.1@1499.92,1096.88
FTDI_UART_RX: R118.1 U27.38 | length 151
  Top Layer w10.8: v2(1228.86,1035.99) 1228.86,1048.54 1235.73,1055.41 R118.1@1235.73,1067.91
  Bottom Layer w8.7: v2(1228.86,1035.99) 1228.86,1052.68 1234.32,1058.14 1293.52,1058.14 1293.56,1058.1 1325.29,1058.1 U27.38@1325.89,1057.51
FTDI_UART_TX: R119.1 U27.39 | length 72.2
  Top Layer w10.8: v2(1273.78,1036.7) 1274.73,1037.64 1291.68,1037.64 R119.1@1292.63,1038.59
  Bottom Layer w8.7: v2(1273.78,1036.7) 1274.91,1037.82 U27.39@1325.89,1037.82
FTDI_UARTA_RX: R118.2 U16.4 | length 1123.8
  Top Layer w10.8: R118.2@1195.37,1067.91 1195.37,1087.48 1212.36,1104.47 v2(1212.36,1105.6) ; v2(1201.74,1817.64) 1214.65,1804.74 U16.4@1214.65,1762.65
  L3_SIG1 w6: v2(1201.74,1817.64) 1201.74,1830.15 1190.46,1841.44 1121.23,1841.44 1020.32,1740.53 1020.32,1551.47 997.87,1529.01 997.87,1243.61 1136.45,1105.03 1211.79,1105.03 v2(1212.36,1105.6)
FTDI_UARTA_TX: R119.2 U16.2 | length 805.8
  Top Layer w6: 1166.83,1715.82 1175.28,1724.26 U16.2@1175.28,1762.65
  Top Layer w10.8: 1166.83,1715.82 1166.83,1687.31 1171.49,1682.65 v2(1171.49,1680.7) ; v2(1265.01,1137.94) 1265.01,1136.14 1257.78,1128.91 1257.78,1085.27 1264.1,1078.94 R119.2@1292.63,1078.94
  L3_SIG1 w6: v2(1171.49,1680.7) 1194.27,1657.93 1194.27,1387.49 1237.96,1343.79 1237.96,1227.64 1210.86,1200.54 1210.86,1155.67 1228.6,1137.94 v2(1265.01,1137.94)
FTDI_USBD_N: J10.2 U27.7 U29.1 | length 2809.7
  Top Layer w7.5: U29.1@2894.05,1645.56 2896.08,1647.59 2904.75,1647.59 2906.51,1649.35 2943.93,1649.35 2949.7,1643.58 2955.39,1643.58 2961.64,1649.83 2973.11,1649.83 2976.03,1646.91 3000.8,1646.91 J10.2@3004.92,1642.79
  Bottom Layer w6: U27.7@888.88,978.77 919.98,978.77 924.2,982.99 1051.43,982.99 1109.63,924.78 1183.99,924.78 1285.41,823.37 1477.68,823.37 1691.35,1037.03 2353.08,1037.03 2412.52,1096.48 2412.52,1156.12 2460.64,1204.24 2751.02,1204.24 2869.22,1322.44 2869.22,1626.53 2892.27,1649.58 2943.3,1649.58 2949.3,1643.58 v2(2952.54,1643.58)
FTDI_USBD_P: J10.3 U27.8 U29.2 | length 2809.8
  Top Layer w7.5: U29.2@2895.04,1665.25 2897.07,1663.22 2904.75,1663.22 2907.12,1660.85 2943.02,1660.85 2949.76,1667.59 2955.39,1667.59 2961.64,1661.33 2973.11,1661.33 2976.03,1664.25 3000.8,1664.25 J10.3@3004.92,1668.38
  Bottom Layer w6: U27.8@888.88,998.45 919.98,998.45 924.45,993.99 1055.99,993.99 1114.19,935.78 1188.55,935.78 1289.96,834.37 1473.13,834.37 1686.79,1048.03 2348.52,1048.03 2401.52,1101.03 2401.52,1160.68 2456.08,1215.24 2746.47,1215.24 2858.22,1327 2858.22,1631.09 2887.71,1660.58 2943.29,1660.58 2950.3,1667.59 v2(2952.55,1667.59)
FTDI_USBID: J10.4 U29.4 | length 200
  Top Layer w10.8: U29.4@2871.42,1684.93 2871.42,1686.46 2871.04,1686.84 2871.04,1702.21 2862.75,1710.5 2862.75,1722.23 2869.07,1728.55 2931.1,1728.55 2965.68,1693.97 J10.4@3004.92,1693.97
FTDI_VBUS: C157.2 J10.1 L8.1 R259.2
FTDI_VCORE: C139.1 C140.1 C143.1 C144.1 U27.12 U27.37 U27.49 U27.64 | length 1533.3
  Top Layer w20: v2(1001.98,1047.62) 1001.98,957.82 v2(1023.22,936.58) 1049.53,936.58 1091.73,894.38 1246.43,894.38 1296.15,844.67 v2(1296.15,799.82)
  Bottom Layer w9: 1250.6,1077.19 U27.37@1325.89,1077.19
  Bottom Layer w10: U27.12@888.88,1077.27 972.33,1077.27 ; 1255.02,746.39 U27.49@1255.02,789.79
  Bottom Layer w12: C140.1@821.09,1098.36 826.9,1092.55 826.9,1084.45 834.06,1077.29 U27.12@888.88,1077.29 ; C139.1@959.67,709.97 959.67,819.21 953.62,825.25 953.62,868.18 972.06,886.61 972.06,918.01 990.62,936.58 v2(1023.22,936.58) ; 972.33,1077.27 v2(1001.98,1047.62) 1084.91,1047.62 1114.48,1077.19 1250.6,1077.19 ; 1255.02,746.39 1263.81,737.6 1278.16,737.6 1290.93,724.83 1319.45,724.83 1334.69,740.07 C144.1@1338.63,740.07 1338.63,788.34 C143.1@1338.47,788.5 1307.47,788.5 v2(1296.15,799.82)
